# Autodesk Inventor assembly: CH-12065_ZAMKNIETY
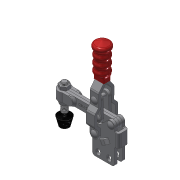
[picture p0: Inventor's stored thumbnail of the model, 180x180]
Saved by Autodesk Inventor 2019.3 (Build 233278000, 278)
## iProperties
Company: Î¢ÈíÖÐ¹ú
Created: 2015-08
Part Number: CH-12065_ZAMKNIETY
Material: Ogólny
Description: STEP AP203
Document SubType Name: Assembly
Designer: CADENGINEERING4
Sending System: SolidWorks 2012
Preprocessor: SwSTEP 2.0
Title: CH-12065.STEP
Author: Î¢ÈíÓÃ»§
Revision Number: ÈÎºÎ
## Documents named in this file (10)
- D:\Vault_2016\Projekty\NASZ KATALOG\CLAMPTEK\STRONA\Vertical toggle clamp\CH-12065\CH-12065_ZAMKNIETY.iam
- D:\Vault_2016\Projekty\NASZ KATALOG\CLAMPTEK\STEP FILES\Vertical toggle clamp\CH-12065\CH-12055-01 STRAIGHT BASE.ipt
- D:\Vault_2016\Projekty\NASZ KATALOG\CLAMPTEK\STEP FILES\Vertical toggle clamp\CH-12065\CH-12050-03 STRAIGHT HANDLE.ipt
- D:\Vault_2016\Projekty\NASZ KATALOG\CLAMPTEK\STEP FILES\Vertical toggle clamp\CH-12065\CH-12050-04 CONNECTING-PLATE.ipt
- D:\Vault_2016\Projekty\NASZ KATALOG\CLAMPTEK\STEP FILES\Vertical toggle clamp\CH-12065\CH-12050-05.ipt
- D:\Vault_2016\Projekty\NASZ KATALOG\CLAMPTEK\STEP FILES\Vertical toggle clamp\CH-12065\CH-12050-06.ipt
- D:\Vault_2016\Projekty\NASZ KATALOG\CLAMPTEK\STEP FILES\Vertical toggle clamp\CH-12065\CH-12050-07.ipt
- D:\Vault_2016\Projekty\NASZ KATALOG\CLAMPTEK\STEP FILES\Vertical toggle clamp\CH-12065\CH-FC-14134 Nut.ipt
- D:\Vault_2016\Projekty\NASZ KATALOG\CLAMPTEK\STEP FILES\Vertical toggle clamp\CH-12065\CH-FC-14134 SPINDLE SUPPLIED.ipt
- D:\Vault_2016\Projekty\NASZ KATALOG\CLAMPTEK\STEP FILES\Vertical toggle clamp\CH-12065\CH-12065-02 SOLID BAR_Ä¬ÈÏ_°´¼Ó¹¤_.ipt
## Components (12 placed, 12 different names)
1. CH-12055-01 STRAIGHT BASE_1
2. CH-12050-03 STRAIGHT HANDLE_2
3. CH-12050-04 CONNECTING-PLATE_3
4. CH-12050-05_4
5. CH-12050-06_5
6. CH-12050-07_6
7. CH-12050-06_7
8. CH-12050-07_8
9. CH-FC-14134 Nut_9
10. CH-FC-14134 SPINDLE SUPPLIED_10
11. CH-FC-14134 Nut_11
12. CH-12065-02 SOLID BAR_Ä¬ÈÏ<°´¼Ó¹¤>_12
